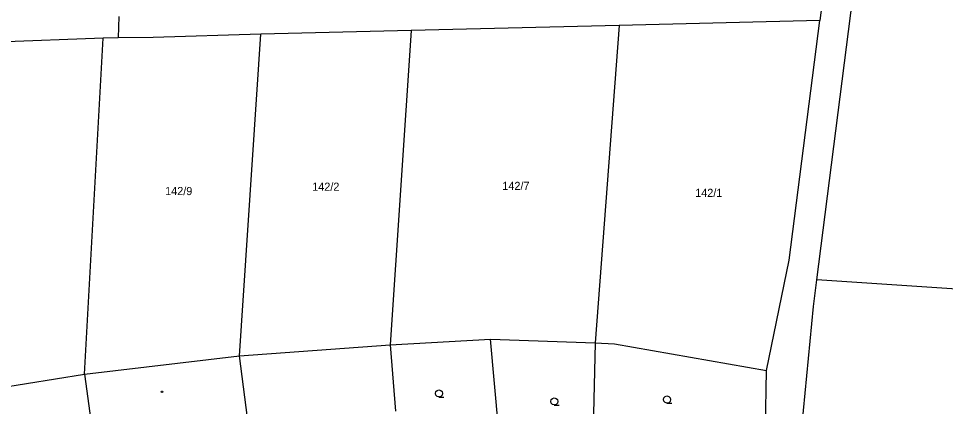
# Model space of a CAD drawing. Extents: x -812394 to -807601, y -1013097 to -1009266.
# Drawn here: x -809612.2 to -809418.3, y -1010671.6 to -1010590.6 of the extents above; entities that cross this region are included whole.
import ezdxf

# ---------------------------------------------------------------- set-up
doc = ezdxf.new("R2010")
doc.units = 0
for name, color, linetype in [('Default', 7, 'Continuous'), ('KN_HRANICE', 7, 'Continuous'), ('KN_KULTURY', 7, 'Continuous'), ('KN_PARCELY', 7, 'Continuous')]:
    doc.layers.add(name, color=color, linetype=linetype)

# ---------------------------------------------------------------- blocks, each defined once
blk = doc.blocks.new('304')
at = {"layer": 'Default'}
blk.add_lwpolyline([(0, 0), (-0.38, 0.1), (-0.65, 0.37), (-0.75, 0.74), (-0.65, 1.11), (-0.38, 1.38), (-0.01, 1.48), (0.36, 1.38), (0.63, 1.11), (0.73, 0.73), (0.63, 0.35), (0.36, 0.08), (-0.02, -0.02), (0.98, -0.02)], dxfattribs=at)
blk = doc.blocks.new('402')
at = {"layer": 'Default'}
blk.add_lwpolyline([(0.09, 0.15), (0.18, 0), (0.09, -0.15), (-0.09, -0.15), (-0.18, 0), (-0.09, 0.15), (0.09, 0.15)], dxfattribs=at)

msp = doc.modelspace()

# ---------------------------------------------------------------- linework, layer by layer
at = {"layer": 'KN_HRANICE'}
for p, q in [((-809445.19, -1010645.2), (-809431.77, -1010540.21)), ((-809440.59, -1010560.03), (-809444.6, -1010590.99)), ((-809591.24, -1010590.16), (-809591.38, -1010594.61)), ((-809486.59, -1010592), (-809530.09, -1010593.05)), ((-809486.59, -1010592), (-809491.57, -1010658.3)), ((-809444.6, -1010590.99), (-809486.59, -1010592)), ((-809450.97, -1010641.06), (-809444.6, -1010590.99)), ((-809594.54, -1010594.65), (-809642.04, -1010596.56)), ((-809598.46, -1010664.88), (-809594.54, -1010594.65)), ((-809591.38, -1010594.61), (-809594.54, -1010594.65)), ((-809584.05, -1010594.51), (-809591.38, -1010594.61)), ((-809561.54, -1010593.83), (-809584.05, -1010594.51)), ((-809565.97, -1010661.03), (-809561.54, -1010593.83)), ((-809530.09, -1010593.05), (-809561.54, -1010593.83)), ((-809530.09, -1010593.05), (-809534.45, -1010658.78)), ((-809455.72, -1010664.14), (-809450.97, -1010641.06)), ((-809445.9, -1010650.77), (-809445.19, -1010645.2)), ((-809388.09, -1010648.93), (-809445.19, -1010645.2)), ((-809448.82, -1010680.59), (-809445.9, -1010650.77)), ((-809534.45, -1010658.78), (-809513.45, -1010657.55)), ((-809513.45, -1010657.55), (-809491.57, -1010658.3)), ((-809511.21, -1010683.19), (-809513.45, -1010657.55)), ((-809491.57, -1010658.3), (-809492.27, -1010687)), ((-809491.57, -1010658.3), (-809487.51, -1010658.54)), ((-809487.51, -1010658.54), (-809455.72, -1010664.14)), ((-809565.97, -1010661.03), (-809534.45, -1010658.78)), ((-809534.45, -1010658.78), (-809533.33, -1010672.61)), ((-809598.46, -1010664.88), (-809565.97, -1010661.03)), ((-809564.36, -1010674), (-809565.97, -1010661.03)), ((-809456.08, -1010681.32), (-809455.72, -1010664.14)), ((-809633.83, -1010670.62), (-809598.46, -1010664.88)), ((-809598.46, -1010664.88), (-809596.67, -1010677.83))]:
    msp.add_line(p, q, dxfattribs=at)

# ---------------------------------------------------------------- block references
at = {"layer": 'KN_KULTURY'}
for name, p in [('402', (-809582.2, -1010668.57)), ('304', (-809524.25, -1010669.64)), ('304', (-809500.12, -1010671.31)), ('304', (-809476.55, -1010670.92))]:
    msp.add_blockref(name, p, dxfattribs=at)

# ---------------------------------------------------------------- texts
at = {"layer": 'KN_PARCELY'}
for s, p in [('142/9', (-809581.56, -1010627.46)), ('142/2', (-809550.79, -1010626.56)), ('142/7', (-809511.01, -1010626.39)), ('142/1', (-809470.66, -1010627.85))]:
    msp.add_text(s, height=1.7, dxfattribs=at).set_placement(p)

doc.saveas('drawing.dxf')
